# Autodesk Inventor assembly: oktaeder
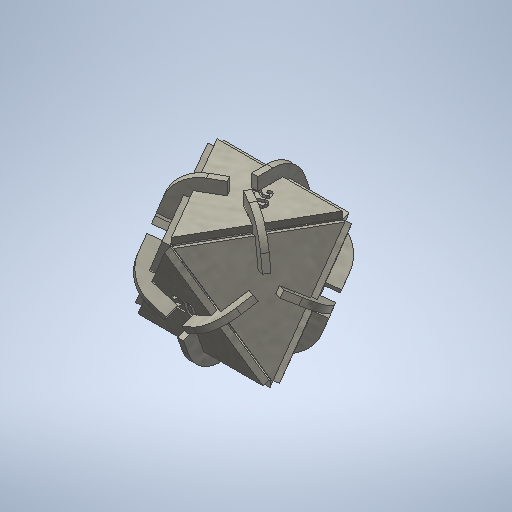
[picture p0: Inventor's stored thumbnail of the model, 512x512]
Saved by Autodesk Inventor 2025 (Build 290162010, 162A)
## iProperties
Created: 2025-02
Part Number: oktaeder
Material: Generisch
Document SubType Name: Assembly
Designer: BennF
Author: BennF
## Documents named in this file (3)
- C:\Users\BennF\OneDrive - Technische Universität Ilmenau\FabAcademy\week03\octahedron.iam
- C:\Users\BennF\OneDrive - Technische Universität Ilmenau\FabAcademy\week03\triangular_tile.ipt
- C:\Users\BennF\OneDrive - Technische Universität Ilmenau\FabAcademy\week03\conector_109.ipt
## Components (20 placed, 2 different names)
1. triangular_tile:1 — Mate:1, Mate:2, Mate:3, Mate:22, Mate:23, Mate:24
2. triangular_tile:2
3. triangular_tile:3
4. triangular_tile:4
5. triangular_tile:5
6. triangular_tile:6 — Mate:40, Mate:41, Mate:42, Mate:43, Mate:44, Mate:45
7. triangular_tile:7 — Mate:46, Mate:47, Mate:48, Mate:49, Mate:50, Mate:51
8. triangular_tile:8 — Mate:52, Mate:53, Mate:54, Mate:55
9. conector_109:1 — Mate:1, Mate:2, Mate:3, Mate:4, Mate:5, Mate:6
10. conector_109:2 — Mate:7, Mate:8, Mate:9, Mate:10, Mate:11, Mate:12
11. conector_109:3 — Mate:13, Mate:14, Mate:15, Mate:16, Mate:17, Mate:18
12. conector_109:4 — Mate:19, Mate:20, Mate:21
13. conector_109:5 — Mate:22, Mate:23, Mate:24, Mate:34, Mate:35, Mate:36
14. conector_109:6 — Mate:25, Mate:26, Mate:27
15. conector_109:7 — Mate:28, Mate:29, Mate:30
16. conector_109:8 — Mate:31, Mate:32, Mate:33
17. conector_109:9 — Mate:37, Mate:38, Mate:39, Mate:40, Mate:41, Mate:42
18. conector_109:10 — Mate:43, Mate:44, Mate:45, Mate:46, Mate:47, Mate:48
19. conector_109:11 — Mate:49, Mate:50, Mate:51, Mate:52, Mate:53, Mate:54
20. conector_109:12 — Mate:55, Mate:56, Mate:57
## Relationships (57: Mate 57)
- Mate:1: triangular_tile:1 ↔ conector_109:1
- Mate:2: triangular_tile:1 ↔ conector_109:1
- Mate:3: triangular_tile:1 ↔ conector_109:1
- Mate:4: conector_109:1
- Mate:5: conector_109:1
- Mate:6: conector_109:1
- Mate:7: conector_109:2
- Mate:8: conector_109:2
- Mate:9: conector_109:2
- Mate:10: conector_109:2
- Mate:11: conector_109:2
- Mate:12: conector_109:2
- Mate:13: conector_109:3
- Mate:14: conector_109:3
- Mate:15: conector_109:3
- Mate:16: conector_109:3
- Mate:17: conector_109:3
- Mate:18: conector_109:3
- Mate:19: conector_109:4
- Mate:20: conector_109:4
- Mate:21: conector_109:4
- Mate:22: triangular_tile:1 ↔ conector_109:5
- Mate:23: triangular_tile:1 ↔ conector_109:5
- Mate:24: triangular_tile:1 ↔ conector_109:5
- Mate:25: conector_109:6
- Mate:26: conector_109:6
- Mate:27: conector_109:6
- Mate:28: conector_109:7
- Mate:29: conector_109:7
- Mate:30: conector_109:7
- Mate:31: conector_109:8
- Mate:32: conector_109:8
- Mate:33: conector_109:8
- Mate:34: conector_109:5
- Mate:35: conector_109:5
- Mate:36: conector_109:5
- Mate:37: conector_109:9
- Mate:38: conector_109:9
- Mate:39: conector_109:9
- Mate:40: triangular_tile:6 ↔ conector_109:9
- Mate:41: triangular_tile:6 ↔ conector_109:9
- Mate:42: triangular_tile:6 ↔ conector_109:9
- Mate:43: triangular_tile:6 ↔ conector_109:10
- Mate:44: triangular_tile:6 ↔ conector_109:10
- Mate:45: triangular_tile:6 ↔ conector_109:10
- Mate:46: triangular_tile:7 ↔ conector_109:10
- Mate:47: triangular_tile:7 ↔ conector_109:10
- Mate:48: triangular_tile:7 ↔ conector_109:10
- Mate:49: triangular_tile:7 ↔ conector_109:11
- Mate:50: triangular_tile:7 ↔ conector_109:11
- Mate:51: triangular_tile:7 ↔ conector_109:11
- Mate:52: triangular_tile:8 ↔ conector_109:11
- Mate:53: triangular_tile:8 ↔ conector_109:11
- Mate:54: triangular_tile:8 ↔ conector_109:11
- Mate:55: triangular_tile:8 ↔ conector_109:12
- Mate:56: conector_109:12
- Mate:57: conector_109:12
